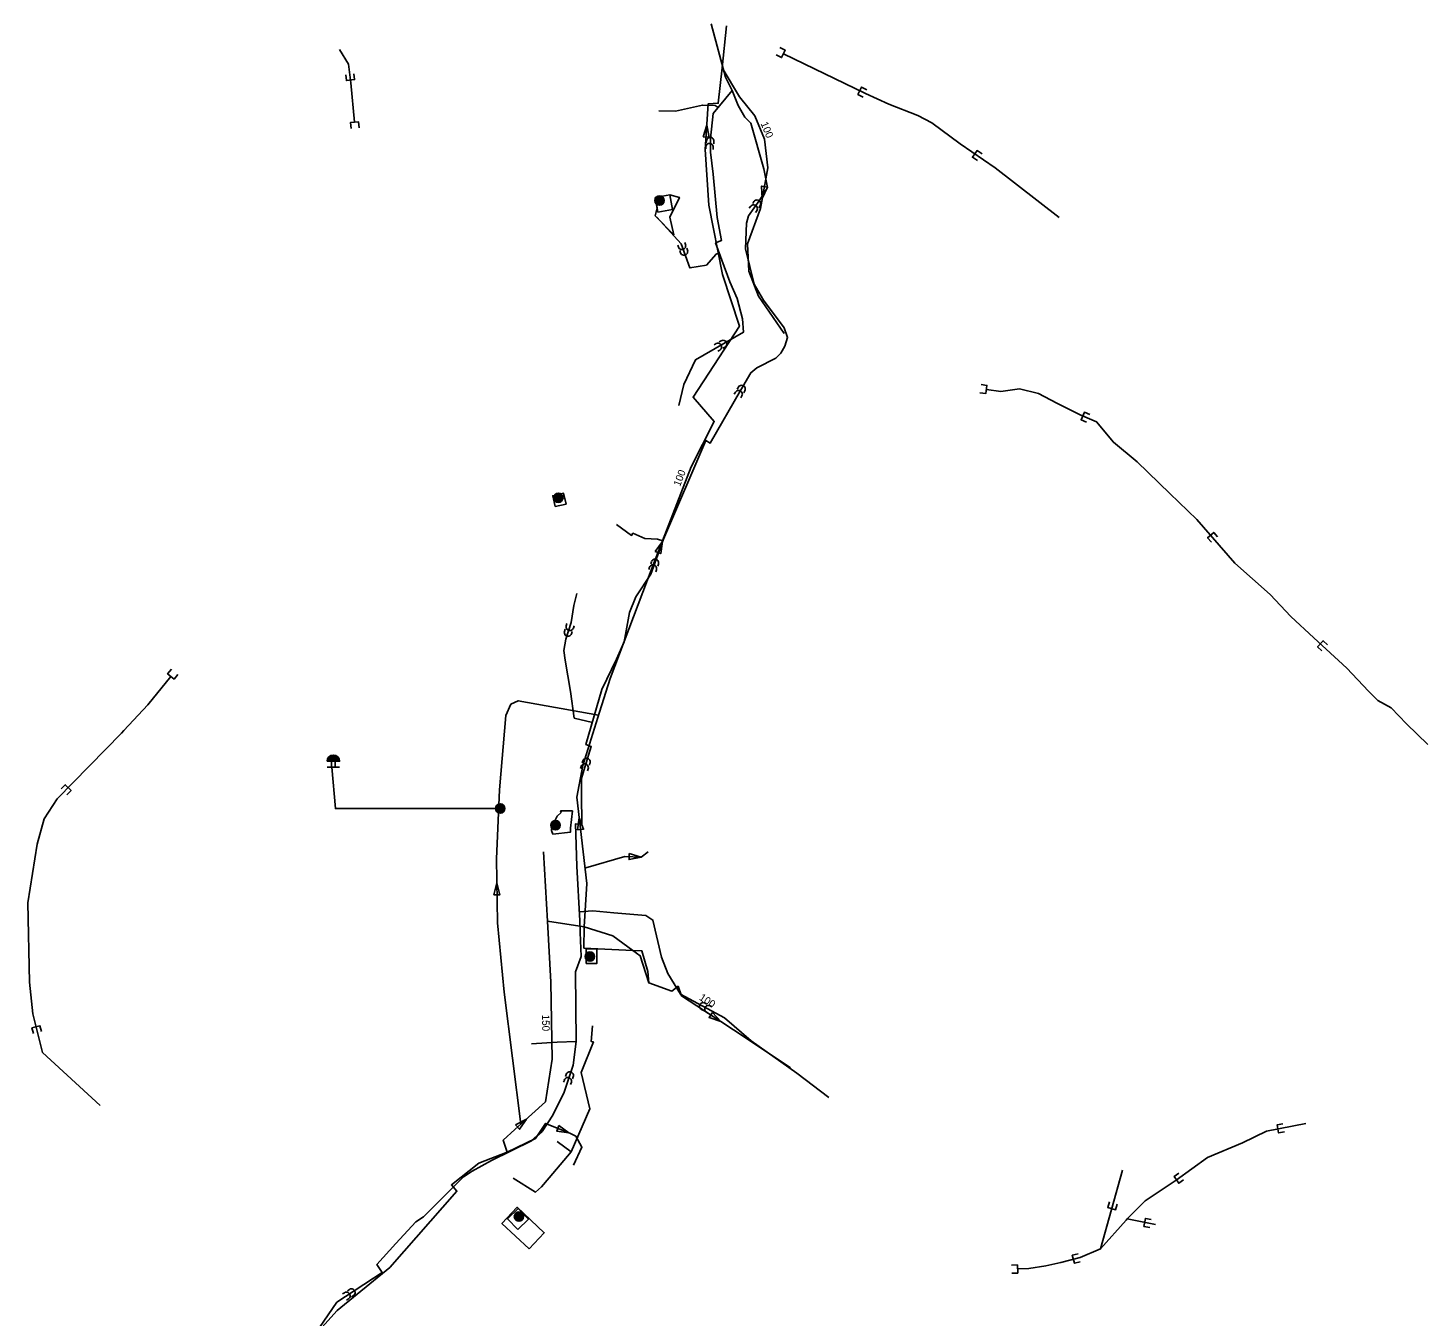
# Model space of a CAD drawing. Extents: x -545007 to -535309, y -1042871 to -1037511.
# Drawn here: x -543352 to -541467, y -1040154 to -1038419 of the extents above; entities that cross this region are included whole.
import ezdxf

# ---------------------------------------------------------------- set-up
doc = ezdxf.new("R2010")
doc.units = 0
for name, color, linetype in [('Vrstva 17', 7, 'Continuous'), ('Vrstva 3', 7, 'Continuous'), ('Vrstva 32', 7, 'Continuous'), ('Vrstva 33', 7, 'Continuous'), ('Vrstva 55', 7, 'Continuous'), ('Vrstva 56', 7, 'Continuous'), ('Vrstva 7', 7, 'Continuous')]:
    doc.layers.add(name, color=color, linetype=linetype)

msp = doc.modelspace()

# ---------------------------------------------------------------- linework, layer by layer
at = {"layer": 'Vrstva 17'}
for p, q in [((-542949.2, -1039414.1), (-542932.5, -1039414.1)), ((-542943.5, -1039406.4), (-542943.5, -1039414.1)), ((-542938.3, -1039406.4), (-542938.3, -1039414.1))]:
    msp.add_line(p, q, dxfattribs=at)
for points in [[(-542949.2, -1039406.4), (-542948.6, -1039403.2), (-542946.8, -1039400.5), (-542944.1, -1039398.7), (-542940.9, -1039398.1), (-542937.7, -1039398.7), (-542935, -1039400.5), (-542933.2, -1039403.2), (-542932.5, -1039406.4)], [(-542948.3, -1039405.6), (-542947.9, -1039403.5), (-542946.2, -1039401.1), (-542943.8, -1039399.4), (-542940.9, -1039398.9), (-542938, -1039399.4), (-542935.5, -1039401.1), (-542933.9, -1039403.5), (-542933.5, -1039405.6)], [(-542947.3, -1039404.8), (-542947.1, -1039403.8), (-542945.6, -1039401.7), (-542943.5, -1039400.2), (-542940.9, -1039399.7), (-542938.3, -1039400.2), (-542936.1, -1039401.7), (-542934.7, -1039403.8), (-542934.5, -1039404.8)], [(-542946.3, -1039404), (-542945.1, -1039402.2), (-542943.1, -1039400.9), (-542940.9, -1039400.5), (-542938.6, -1039400.9), (-542936.7, -1039402.2), (-542935.5, -1039404)], [(-542944.8, -1039403.2), (-542944.5, -1039402.8), (-542942.8, -1039401.7), (-542940.9, -1039401.3), (-542938.9, -1039401.7), (-542937.3, -1039402.8), (-542937, -1039403.2)], [(-542942.3, -1039402.4), (-542940.9, -1039402.1), (-542939.5, -1039402.4)]]:
    msp.add_lwpolyline(points, close=True, dxfattribs=at)
at = {"layer": 'Vrstva 3'}
for points in [[(-542516, -1039704.9), (-542517.5, -1039689.6), (-542525.4, -1039661.9), (-542537.6, -1039661.3), (-542603.5, -1039657.9), (-542602.9, -1039629.3), (-542599.4, -1039571.2), (-542613.1, -1039454.9), (-542604.9, -1039412), (-542582.5, -1039340.3), (-542568.2, -1039294.8), (-542511.4, -1039145.5), (-542459.2, -1039009.9), (-542428, -1038948.6), (-542456.4, -1038915.8), (-542394.1, -1038820.5), (-542417, -1038750.9), (-542435.4, -1038657.5), (-542440, -1038582.4), (-542436.3, -1038521), (-542422.5, -1038520.1), (-542417.5, -1038472.3), (-542411.5, -1038415.7)], [(-542417.5, -1038472.3), (-542394.1, -1038511.7), (-542373.1, -1038537.3), (-542360.2, -1038568.5), (-542355.6, -1038606.9), (-542365.7, -1038661.9), (-542383.1, -1038709.5), (-542381.3, -1038746.2), (-542368.5, -1038780.1), (-542333.7, -1038830.4)], [(-542583.8, -1039344.5), (-542691.8, -1039324.8), (-542701.7, -1039329.6), (-542708.7, -1039344.7), (-542717.1, -1039445), (-542721.3, -1039537.7), (-542720, -1039623.9), (-542710.9, -1039717.2), (-542688.4, -1039895.1)], [(-542717.1, -1039470), (-542938.2, -1039470), (-542943.1, -1039414.1)], [(-542652.7, -1039621.8), (-542658, -1039528.2)], [(-542600.7, -1039549.8), (-542548.3, -1039534.5), (-542526.5, -1039535.5), (-542516.9, -1039528.2)], [(-542964.6, -1040178.1), (-542935.7, -1040145.9), (-542864.6, -1040088.1), (-542774.4, -1039985.2), (-542781.8, -1039977), (-542745.1, -1039947.7), (-542706.6, -1039933), (-542712.1, -1039916.5), (-542696.5, -1039902.4), (-542655.3, -1039865.2), (-542646.1, -1039807.5), (-542648, -1039704), (-542652.7, -1039621.8), (-542602.9, -1039629.3), (-542564.6, -1039641.7), (-542537.6, -1039661.3), (-542527.9, -1039668.3), (-542516, -1039704.9), (-542484.9, -1039715.9), (-542476.6, -1039709.5), (-542472, -1039722.3), (-542419.3, -1039756.7), (-542385, -1039779.1), (-542325.4, -1039819.4)], [(-542698.7, -1039967.9), (-542668.5, -1039986.7), (-542660.7, -1039979.5), (-542650.2, -1039967.3), (-542620.7, -1039932.3), (-542595.7, -1039874.4), (-542607.1, -1039825.6), (-542590.6, -1039784.3), (-542593.8, -1039783.7), (-542591.8, -1039762.8)], [(-542706.6, -1039933), (-542668.6, -1039914.6), (-542655.1, -1039894.1), (-542622.3, -1039907.2), (-542614.4, -1039911.1), (-542606.1, -1039926.1), (-542617.4, -1039950.3)], [(-542620.7, -1039932.3), (-542639.3, -1039918.7)]]:
    msp.add_lwpolyline(points, dxfattribs=at)
for points in [[(-542442.9, -1038565.3), (-542435, -1038565.8), (-542438, -1038549.6)], [(-542356.4, -1038633.3), (-542364.3, -1038631.8), (-542363.2, -1038648.3)], [(-542507.3, -1039123.7), (-542499.9, -1039126.6), (-542497.8, -1039110.2)], [(-542612, -1039498.9), (-542604, -1039497.9), (-542609.9, -1039482.5)], [(-542542.3, -1039530.7), (-542542.7, -1039538.7), (-542526.5, -1039535.5)], [(-542724.6, -1039586.3), (-542716.6, -1039586.1), (-542720.8, -1039570.2)], [(-542430.5, -1039744.7), (-542434.9, -1039751.4), (-542419.3, -1039756.7)], [(-542695.5, -1039896.1), (-542690.1, -1039902), (-542680.9, -1039888.3)], [(-542637.1, -1039897), (-542640.1, -1039904.4), (-542623.7, -1039906.6)]]:
    msp.add_lwpolyline(points, close=True, dxfattribs=at)
at = {"layer": 'Vrstva 32'}
for p, q in [((-542438.3, -1038570.6), (-542438.7, -1038573.6)), ((-542428.4, -1038571.6), (-542428.7, -1038574.6)), ((-542439.2, -1038578.6), (-542439.5, -1038581.6)), ((-542429.2, -1038579.6), (-542429.5, -1038582.6)), ((-542379, -1038659.1), (-542380.8, -1038661.6)), ((-542374.5, -1038652.6), (-542376.2, -1038655)), ((-542370.8, -1038664.9), (-542372.6, -1038667.3)), ((-542366.3, -1038658.3), (-542368, -1038660.8)), ((-542476.1, -1038713.9), (-542477.1, -1038711.1)), ((-542473.4, -1038721.5), (-542474.4, -1038718.6)), ((-542466.7, -1038710.5), (-542467.7, -1038707.7)), ((-542464, -1038718.1), (-542465, -1038715.2)), ((-542425.5, -1038843.9), (-542428.1, -1038845.4)), ((-542420.5, -1038852.6), (-542423.1, -1038854.1)), ((-542418.5, -1038839.9), (-542421.1, -1038841.4)), ((-542413.5, -1038848.6), (-542416.2, -1038850.1)), ((-542399.4, -1038909.3), (-542400.9, -1038911.9)), ((-542395.4, -1038902.4), (-542396.9, -1038905)), ((-542386.8, -1038907.4), (-542388.2, -1038910)), ((-542390.7, -1038914.3), (-542392.2, -1038916.9)), ((-542512.5, -1039137.6), (-542513.5, -1039140.4)), ((-542515.2, -1039145.1), (-542516.2, -1039147.9)), ((-542505.8, -1039148.4), (-542506.8, -1039151.3)), ((-542503.1, -1039140.9), (-542504.1, -1039143.7)), ((-542629.7, -1039231.5), (-542628.7, -1039228.6)), ((-542627.2, -1039223.9), (-542626.3, -1039221)), ((-542620.1, -1039234.6), (-542619.2, -1039231.7)), ((-542617.7, -1039227), (-542616.8, -1039224.1)), ((-542607.2, -1039413.4), (-542608.1, -1039416.3)), ((-542604.8, -1039405.8), (-542605.7, -1039408.7)), ((-542597.6, -1039416.4), (-542598.5, -1039419.3)), ((-542595.3, -1039408.8), (-542596.1, -1039411.6)), ((-542445.2, -1039740.8), (-542442.5, -1039742.2)), ((-542440.4, -1039732), (-542437.8, -1039733.4)), ((-542433.4, -1039735.8), (-542430.7, -1039737.2)), ((-542438.1, -1039744.6), (-542435.5, -1039746)), ((-542629.8, -1039835.7), (-542630.8, -1039838.6)), ((-542627.4, -1039828.1), (-542628.3, -1039831)), ((-542617.8, -1039831.2), (-542618.8, -1039834.1)), ((-542620.3, -1039838.8), (-542621.3, -1039841.7)), ((-542919.3, -1040117.7), (-542921.8, -1040119.4)), ((-542926, -1040122.1), (-542928.5, -1040123.8)), ((-542920.5, -1040130.5), (-542923.1, -1040132.1)), ((-542913.8, -1040126.1), (-542916.4, -1040127.8))]:
    msp.add_line(p, q, dxfattribs=at)
for points in [[(-542432.3, -1038413.3), (-542412.6, -1038485.1), (-542403.6, -1038503.1), (-542395.9, -1038523.2), (-542386.6, -1038539.1), (-542378.7, -1038547.1), (-542361.1, -1038608.3), (-542356.3, -1038633.5), (-542366.6, -1038650), (-542381.7, -1038671.7), (-542384.5, -1038681.8), (-542385.9, -1038716.4), (-542374.3, -1038763.7), (-542361.4, -1038785.2), (-542333.6, -1038822.7), (-542329.3, -1038835.6), (-542332.7, -1038847.2), (-542338.2, -1038856.9), (-542345.1, -1038863.3), (-542370.7, -1038876.7), (-542378.7, -1038883.2), (-542392.4, -1038907.2), (-542433.5, -1038978.1), (-542439.4, -1038974.3), (-542496.5, -1039107.3), (-542513.2, -1039154.4), (-542533.5, -1039185.1), (-542542, -1039206.1), (-542549.3, -1039245.6), (-542559.4, -1039268.8), (-542579.3, -1039309.5), (-542600.8, -1039384), (-542593.5, -1039386.4), (-542602.2, -1039414.1), (-542606.7, -1039429.7), (-542606.8, -1039451.1), (-542606.1, -1039491.1), (-542614.8, -1039490.8), (-542612.9, -1039547.5), (-542609.1, -1039621.2), (-542608.4, -1039637.2), (-542607.2, -1039669.2), (-542614.8, -1039690), (-542614.1, -1039783.8), (-542618.1, -1039815.9), (-542629.9, -1039851.9), (-542645.4, -1039883.1), (-542659.7, -1039904.9), (-542674.2, -1039917.4), (-542727.7, -1039944.2), (-542754, -1039958.6), (-542765.6, -1039966.2), (-542780.1, -1039980.4), (-542791.2, -1039991.7), (-542819.6, -1040019.8), (-542829.6, -1040026.5), (-542856.6, -1040055.7), (-542882.3, -1040084.1), (-542875.1, -1040094.9), (-542936.4, -1040134.9), (-542965.5, -1040177.5)], [(-542403.6, -1038503.1), (-542429.5, -1038533.9), (-542433, -1038567.5), (-542433, -1038585.8), (-542429.4, -1038615.5), (-542424.2, -1038674), (-542418.3, -1038705.2), (-542426.2, -1038708.3), (-542417.9, -1038731.5), (-542406.8, -1038760.6), (-542397.3, -1038783.2), (-542389.7, -1038810.3), (-542388.7, -1038828.6), (-542453.4, -1038865.7), (-542468.8, -1038898.8), (-542475.8, -1038927.2)], [(-542502.5, -1038530.3), (-542480.3, -1038531), (-542443.9, -1038522.6), (-542426.6, -1038523), (-542422.8, -1038525.9)], [(-542421.4, -1038721.8), (-542425.5, -1038723.6), (-542438.5, -1038738.2), (-542460.7, -1038742), (-542472.3, -1038709.7), (-542505.1, -1038673.5)], [(-542497.3, -1039109.5), (-542504.5, -1039107.1), (-542521.3, -1039106.2), (-542537.4, -1039099.3), (-542539.3, -1039102.2), (-542559.6, -1039087.5)], [(-542592.1, -1039354), (-542616.4, -1039348.3), (-542621.6, -1039312.6), (-542628.5, -1039270.4), (-542630.6, -1039257.2), (-542627.8, -1039242), (-542620.5, -1039219.5), (-542617.1, -1039196.6), (-542613.2, -1039180.3)], [(-542273.7, -1039859.2), (-542316.6, -1039826.6), (-542378.2, -1039783), (-542414.3, -1039751.8), (-542473.2, -1039719.9), (-542490.5, -1039692.2), (-542498.8, -1039670.1), (-542510.6, -1039620.2), (-542520.2, -1039614), (-542563.2, -1039610.5), (-542591.6, -1039607.7), (-542609.7, -1039609.1)], [(-542674, -1039786.8), (-542639.7, -1039784.7), (-542614.1, -1039783.8)]]:
    msp.add_lwpolyline(points, dxfattribs=at)
for centre, start, end in [((-542433.4, -1038571.1), 354.1206, 174.1217), ((-542434.2, -1038579.1), 354.1206, 174.1217), ((-542374.9, -1038662), 325.1817, 145.1828), ((-542370.4, -1038655.4), 325.1817, 145.1828), ((-542471.4, -1038712.2), 199.9019, 19.9029), ((-542468.7, -1038719.8), 199.9019, 19.9029), ((-542423, -1038848.3), 299.7811, 119.7821), ((-542416, -1038844.3), 299.7811, 119.7821), ((-542395.1, -1038911.8), 330.2153, 150.2164), ((-542391.1, -1038904.9), 330.2153, 150.2164), ((-542507.8, -1039139.2), 340.553, 160.554), ((-542510.5, -1039146.8), 340.553, 160.554), ((-542624.9, -1039233), 162.1087, 342.1097), ((-542622.4, -1039225.4), 162.1087, 342.1097), ((-542600, -1039407.3), 342.6448, 162.6459), ((-542602.4, -1039414.9), 342.6448, 162.6459), ((-542442.8, -1039736.4), 61.5746, 241.5757), ((-542435.7, -1039740.2), 61.5746, 241.5757), ((-542625.1, -1039837.3), 341.8902, 161.8912), ((-542622.6, -1039829.7), 341.8902, 161.8912), ((-542916.6, -1040121.9), 303.1256, 123.1267), ((-542923.3, -1040126.3), 303.1256, 123.1267)]:
    msp.add_arc(centre, 5, start, end, dxfattribs=at)
at = {"layer": 'Vrstva 33'}
for points in [[(-542912.3, -1038545.7), (-542917.3, -1038492.6), (-542920.5, -1038467.3), (-542932.7, -1038447.6)], [(-542344.4, -1038455.1), (-542337.2, -1038458.6), (-542332.4, -1038448.7), (-542339.6, -1038445.2)], [(-541963.6, -1038673.8), (-542049.5, -1038607.1), (-542096.7, -1038574.9), (-542135.1, -1038546.5), (-542154, -1038536.7), (-542192.8, -1038521.4), (-542224.2, -1038507.2), (-542334.8, -1038453.6)], [(-542924.2, -1038481.7), (-542923.2, -1038489.6), (-542912.3, -1038488.3), (-542913.3, -1038480.3)], [(-542222.5, -1038501.9), (-542229.7, -1038498.4), (-542234.5, -1038508.3), (-542227.3, -1038511.8)], [(-542906.1, -1038553.1), (-542906.8, -1038545.2), (-542917.8, -1038546.2), (-542917, -1038554.2)], [(-542067.3, -1038588.3), (-542074, -1038583.8), (-542080.2, -1038592.9), (-542073.5, -1038597.4)], [(-542070.2, -1038910), (-542062.3, -1038911.1), (-542060.7, -1038900.2), (-542068.6, -1038899.1)], [(-541534.5, -1039324.6), (-541547, -1039311.9), (-541576.1, -1039281.1), (-541620.7, -1039240), (-541651.3, -1039211.3), (-541679.5, -1039181.6), (-541726.7, -1039139.4), (-541778.1, -1039080.6), (-541814.6, -1039045.8), (-541858.4, -1039003), (-541890.4, -1038976.7), (-541913, -1038949.4), (-541935.3, -1038939.6), (-541966.7, -1038923.9), (-541991.3, -1038911), (-542017, -1038904.8), (-542042, -1038908.5), (-542061.5, -1038905.7)], [(-541922.1, -1038939.4), (-541929.4, -1038936.2), (-541933.9, -1038946.3), (-541926.5, -1038949.5)], [(-541750.1, -1039104.2), (-541755.4, -1039098.2), (-541763.6, -1039105.4), (-541758.4, -1039111.5)], [(-541602.1, -1039249.6), (-541608, -1039244.1), (-541615.5, -1039252.2), (-541609.6, -1039257.6)], [(-543158.9, -1039282.4), (-543164, -1039288.6), (-543155.4, -1039295.6), (-543150.4, -1039289.4)], [(-543159.7, -1039292.1), (-543190.8, -1039330.2), (-543223.2, -1039365), (-543226.3, -1039368.6), (-543312.9, -1039457.1), (-543330.4, -1039484.1), (-543339.9, -1039518.2), (-543352.1, -1039597.1), (-543350, -1039703.8), (-543345.7, -1039746.6), (-543332.7, -1039798.4), (-543254.8, -1039870.2)], [(-541534.5, -1039324.6), (-541516.4, -1039334.5), (-541495.7, -1039356.1), (-541466.8, -1039383.8)], [(-543299.6, -1039451.4), (-543294, -1039445.7), (-543301.9, -1039438), (-543307.5, -1039443.7)], [(-543334.1, -1039770.5), (-543336, -1039762.7), (-543346.7, -1039765.4), (-543344.7, -1039773.2)], [(-541871.9, -1040022.8), (-541847.7, -1039998.4), (-541806.1, -1039970.6), (-541763.5, -1039940.2), (-541716.7, -1039920.4), (-541684.2, -1039904.5), (-541631.5, -1039894.4)], [(-541662.1, -1039894.6), (-541669.9, -1039896.2), (-541667.9, -1039907), (-541660, -1039905.4)], [(-541907.9, -1040063.1), (-541878.4, -1039957.1)], [(-541802.3, -1039961.1), (-541808.8, -1039965.8), (-541802.4, -1039974.7), (-541795.9, -1039970.1)], [(-541895.9, -1039999.7), (-541898.1, -1040007.4), (-541887.5, -1040010.4), (-541885.3, -1040002.7)], [(-542019.5, -1040090.2), (-542004.1, -1040089.5), (-541981.6, -1040086.1), (-541961.4, -1040081.6), (-541935.2, -1040074.7), (-541907.9, -1040063.1), (-541873.4, -1040024.3), (-541871.9, -1040022.8)], [(-541871.9, -1040022.8), (-541833.7, -1040030.2)], [(-541839.4, -1040023.5), (-541847.3, -1040022), (-541849.3, -1040032.8), (-541841.5, -1040034.3)], [(-541938, -1040069.8), (-541945.8, -1040071.8), (-541943, -1040082.5), (-541935.2, -1040080.4)], [(-542027.2, -1040096), (-542019.2, -1040095.7), (-542019.7, -1040084.7), (-542027.7, -1040085.1)]]:
    msp.add_lwpolyline(points, dxfattribs=at)
at = {"layer": 'Vrstva 55'}
for points in [[(-542503.8, -1038666.9), (-542484.2, -1038663.3), (-542487.8, -1038643.6), (-542507.5, -1038647.2), (-542503.8, -1038666.9)], [(-542642.1, -1039063.3), (-542627.5, -1039060), (-542630.8, -1039045.4), (-542645.4, -1039048.7), (-542642.1, -1039063.3)], [(-542645.2, -1039504.4), (-542621.4, -1039501.7), (-542621.4, -1039496.7), (-542619, -1039473.2), (-542634.9, -1039473.2), (-542634.3, -1039475.6), (-542639.4, -1039480.3), (-542642.8, -1039486.7), (-542646.8, -1039493.3), (-542647, -1039499.6), (-542645.2, -1039504.4)], [(-542600.5, -1039678.8), (-542585.9, -1039678.6), (-542585.9, -1039658.8), (-542600.5, -1039659.4), (-542600.5, -1039678.8)], [(-542692.5, -1040037.1), (-542678.1, -1040023.2), (-542692, -1040008.8), (-542706.4, -1040022.7), (-542692.5, -1040037.1)]]:
    msp.add_lwpolyline(points, dxfattribs=at)
at = {"layer": 'Vrstva 56'}
for points in [[(-542482.4, -1038697.5), (-542487.6, -1038673.7), (-542474.9, -1038647), (-542487.8, -1038643.6), (-542507.5, -1038647.2), (-542504.9, -1038661.2), (-542507.5, -1038671.9), (-542482.4, -1038697.5)], [(-542677.4, -1040063.2), (-542656.9, -1040041.3), (-542693.3, -1040007.1), (-542713.8, -1040028.9), (-542677.4, -1040063.2)]]:
    msp.add_lwpolyline(points, dxfattribs=at)
at = {"layer": 'Vrstva 7'}
for centre, radius in [((-542501.6, -1038651.3), 6.3), ((-542501.6, -1038651.3), 5.3), ((-542501.6, -1038651.3), 4.3), ((-542501.6, -1038651.3), 3.3), ((-542501.6, -1038651.3), 2.3), ((-542501.6, -1038651.3), 1.3), ((-542501.6, -1038651.3), 0.3), ((-542637.9, -1039051.4), 6.3), ((-542637.9, -1039051.4), 5.3), ((-542637.9, -1039051.4), 4.3), ((-542637.9, -1039051.4), 3.3), ((-542637.9, -1039051.4), 2.3), ((-542637.9, -1039051.4), 1.3), ((-542637.9, -1039051.4), 0.3), ((-542716.1, -1039470), 6.3), ((-542716.1, -1039470), 5.3), ((-542716.1, -1039470), 4.3), ((-542716.1, -1039470), 3.3), ((-542716.1, -1039470), 2.3), ((-542716.1, -1039470), 1.3), ((-542716.1, -1039470), 0.3), ((-542641.6, -1039492.5), 6.3), ((-542641.6, -1039492.5), 5.3), ((-542641.6, -1039492.5), 4.3), ((-542641.6, -1039492.5), 3.3), ((-542641.6, -1039492.5), 2.3), ((-542641.6, -1039492.5), 1.3), ((-542641.6, -1039492.5), 0.3), ((-542595.3, -1039669.4), 6.3), ((-542595.3, -1039669.4), 5.3), ((-542595.3, -1039669.4), 4.3), ((-542595.3, -1039669.4), 3.3), ((-542595.3, -1039669.4), 2.3), ((-542595.3, -1039669.4), 1.3), ((-542595.3, -1039669.4), 0.3), ((-542690.9, -1040019.6), 6.3), ((-542690.9, -1040019.6), 5.3), ((-542690.9, -1040019.6), 4.3), ((-542690.9, -1040019.6), 3.3), ((-542690.9, -1040019.6), 2.3), ((-542690.9, -1040019.6), 1.3), ((-542690.9, -1040019.6), 0.3)]:
    msp.add_circle(centre, radius, dxfattribs=at)

# ---------------------------------------------------------------- texts
at = {"layer": 'Vrstva 3'}
for s, rotation, p in [('100', 292.3898, (-542365.7, -1038547.4)), ('100', 69.1656, (-542474, -1039037)), ('100', 326.883, (-542449.2, -1039726.9)), ('150', 271.0145, (-542659.9, -1039747.7))]:
    msp.add_text(s, height=10, rotation=rotation, dxfattribs=at).set_placement(p)

doc.saveas('drawing.dxf')
